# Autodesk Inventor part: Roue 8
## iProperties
Author: Philippe
Shininess: 21.0
Angle Display Precision: 2
Document Length Units: 11269
Document Angle Units: 11283
Document Time Units: 11279
Document Mass Units: 11290
Document Length Units Precision: 3
Document Angle Units Precision: 2
Compacted: False
PropertySet Name: _Private Model Information
Created: 2002-01
Part Number: Roue 8
Material: Par défaut
Document SubType Name: Modélisation
Designer: Philippe
Control State: 0
Master: False
Checked Out: False
PropertySet Name: Design Tracking Control
Density: 0.0
Volumn: 0.0
Area: 0.0
PropertySet Name: Model Information
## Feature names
1. Révolution1 [Revolution]
2. Extrusion1
3. Extrusion5
4. Extrusion6
5. Extrusion7
6. Réseau circulaire4 [Circular Pattern]
7. Extrusion8
8. Extrusion9
9. Réseau circulaire5 [Circular Pattern]
10. Extrusion10
11. Extrusion11
